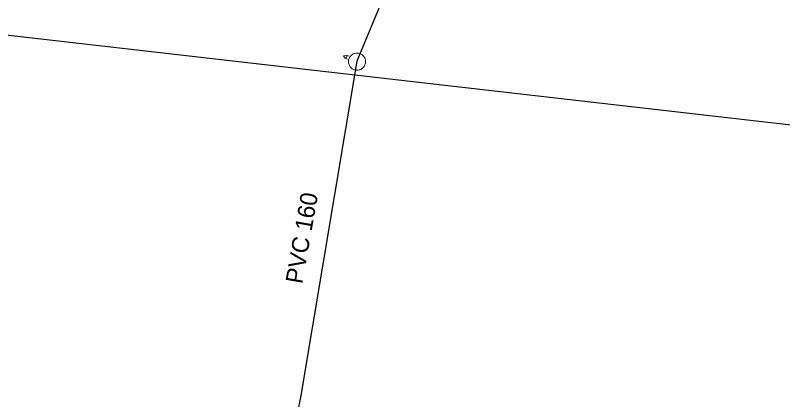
# Model space of a CAD drawing. Extents: x -809028 to -807737, y -990545 to -989489.
# Drawn here: x -808735.91 to -808691.09, y -989779.26 to -989756.83 of the extents above; entities that cross this region are included whole.
import ezdxf

# ---------------------------------------------------------------- set-up
doc = ezdxf.new("R2010")
doc.units = 0
doc.header["$LTSCALE"] = 0.32
for name, color, linetype, lineweight in [('1', 7, 'Continuous', 13), ('17', 7, 'Continuous', 25), ('23', 7, 'Continuous', 13)]:
    doc.layers.add(name, color=color, linetype=linetype, lineweight=lineweight)

msp = doc.modelspace()

# ---------------------------------------------------------------- linework, layer by layer
at = {"layer": '17'}
for points in [[(-808890.538, -989740.302), (-808584.263, -989775.39), (-808526.899, -989811.259)], [(-808694.08, -989752.483), (-808714.649, -989756.377), (-808715.958, -989759.501)], [(-808715.958, -989759.501), (-808719.237, -989779.008), (-808720.573, -989785.741)]]:
    msp.add_lwpolyline(points, dxfattribs=at)
at = {"layer": '23'}
msp.add_line((-808716.521, -989759.171), (-808716.597, -989759.351), dxfattribs=at)
for points in [[(-808716.508, -989759.389), (-808716.645, -989759.331), (-808716.746, -989759.182), (-808716.569, -989759.151), (-808716.432, -989759.208)], [(-808715.757, -989759.067), (-808715.807, -989759.05), (-808715.858, -989759.038), (-808715.909, -989759.033), (-808715.962, -989759.031), (-808716.013, -989759.036), (-808716.066, -989759.046), (-808716.115, -989759.061), (-808716.163, -989759.081), (-808716.209, -989759.106), (-808716.252, -989759.136), (-808716.292, -989759.17), (-808716.328, -989759.209), (-808716.36, -989759.25), (-808716.386, -989759.295), (-808716.409, -989759.342), (-808716.426, -989759.393), (-808716.438, -989759.442), (-808716.444, -989759.496), (-808716.446, -989759.546), (-808716.442, -989759.599), (-808716.43, -989759.651), (-808716.415, -989759.701), (-808716.395, -989759.75), (-808716.37, -989759.796), (-808716.34, -989759.838), (-808716.305, -989759.877), (-808716.268, -989759.913), (-808716.226, -989759.944), (-808716.18, -989759.971), (-808716.134, -989759.994), (-808716.084, -989760.011), (-808716.033, -989760.023), (-808715.981, -989760.03), (-808715.929, -989760.031), (-808715.878, -989760.025), (-808715.826, -989760.015), (-808715.775, -989760.001), (-808715.727, -989759.98), (-808715.681, -989759.955)], [(-808716.444, -989759.496), (-808716.446, -989759.546), (-808716.442, -989759.599), (-808716.43, -989759.651), (-808716.415, -989759.701), (-808716.395, -989759.75), (-808716.37, -989759.796), (-808716.34, -989759.838), (-808716.305, -989759.877), (-808716.268, -989759.913), (-808716.226, -989759.944), (-808716.18, -989759.971), (-808716.134, -989759.994), (-808716.084, -989760.011), (-808716.033, -989760.023), (-808715.981, -989760.03), (-808715.929, -989760.031), (-808715.878, -989760.025), (-808715.826, -989760.015), (-808715.775, -989760.001), (-808715.727, -989759.98), (-808715.681, -989759.955), (-808715.639, -989759.926), (-808715.599, -989759.891), (-808715.563, -989759.854), (-808715.532, -989759.81), (-808715.506, -989759.766), (-808715.483, -989759.719), (-808715.466, -989759.67), (-808715.453, -989759.619), (-808715.447, -989759.566), (-808715.447, -989759.514), (-808715.45, -989759.462), (-808715.46, -989759.411), (-808715.476, -989759.361), (-808715.495, -989759.313), (-808715.521, -989759.267), (-808715.551, -989759.223), (-808715.585, -989759.184), (-808715.624, -989759.148)], [(-808715.681, -989759.955), (-808715.639, -989759.926), (-808715.599, -989759.891), (-808715.563, -989759.854), (-808715.532, -989759.81), (-808715.506, -989759.766), (-808715.483, -989759.719), (-808715.466, -989759.67), (-808715.453, -989759.619), (-808715.447, -989759.566), (-808715.447, -989759.514), (-808715.45, -989759.462), (-808715.46, -989759.411), (-808715.476, -989759.361), (-808715.495, -989759.313), (-808715.521, -989759.267), (-808715.551, -989759.223), (-808715.585, -989759.184), (-808715.624, -989759.148), (-808715.666, -989759.117), (-808715.71, -989759.09), (-808715.757, -989759.067), (-808715.807, -989759.05), (-808715.858, -989759.038), (-808715.909, -989759.033), (-808715.962, -989759.031), (-808716.013, -989759.036), (-808716.066, -989759.046), (-808716.115, -989759.061), (-808716.163, -989759.081), (-808716.209, -989759.106), (-808716.252, -989759.136), (-808716.292, -989759.17), (-808716.328, -989759.209), (-808716.36, -989759.25), (-808716.386, -989759.295), (-808716.409, -989759.342), (-808716.426, -989759.393), (-808716.438, -989759.442), (-808716.444, -989759.496)], [(-808715.624, -989759.148), (-808715.666, -989759.117), (-808715.71, -989759.09), (-808715.757, -989759.067)]]:
    msp.add_lwpolyline(points, dxfattribs=at)

# ---------------------------------------------------------------- texts
at = {"layer": '1'}
msp.add_text('PVC 160 ', height=1, rotation=80, dxfattribs=at).set_placement((-808719.148, -989772.542))

doc.saveas('drawing.dxf')
